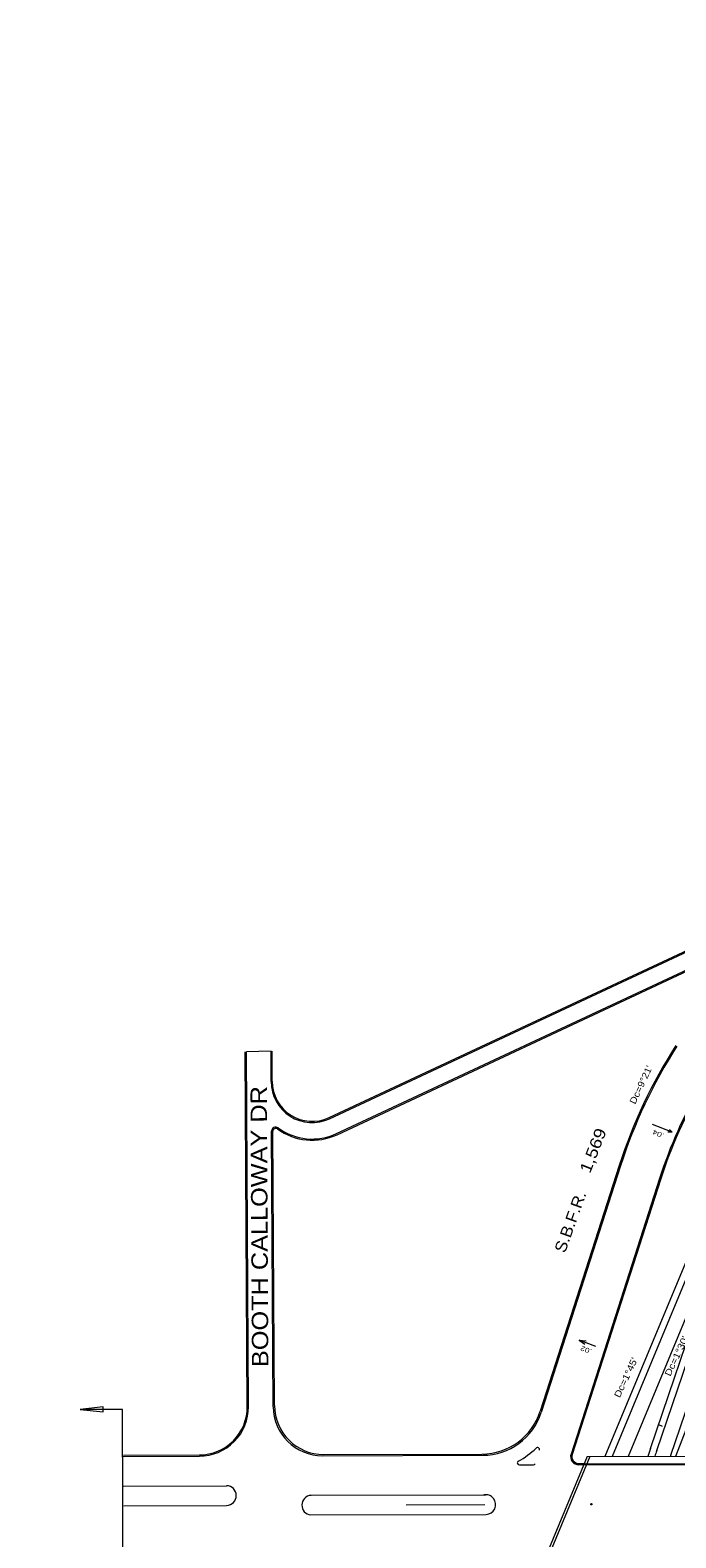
# Model space of a CAD drawing. Extents: x 2354993 to 2372084, y 6966390 to 6990057.
# Drawn here: x 2364099 to 2364884, y 6980481 to 6982315 of the extents above; entities that cross this region are included whole.
import ezdxf
from ezdxf.enums import TextEntityAlignment as Align

# ---------------------------------------------------------------- set-up
doc = ezdxf.new("R2010")
doc.units = 0
doc.header["$LTSCALE"] = 3.2
doc.header["$PDMODE"] = 32
doc.header["$PDSIZE"] = 1.6
for name, color, linetype, lineweight in [('13', 7, 'Continuous', 13), ('15', 7, 'Continuous', 13), ('17', 7, 'Continuous', 13), ('19', 7, 'Continuous', 13), ('25', 7, 'Continuous', 13), ('4', 7, 'Continuous', 13), ('5', 7, 'Continuous', 13), ('8', 7, 'Continuous', 13), ('9', 7, 'Continuous', 13)]:
    doc.layers.add(name, color=color, linetype=linetype, lineweight=lineweight)

msp = doc.modelspace()

# ---------------------------------------------------------------- linework, layer by layer
at = {"layer": '15'}
msp.add_lwpolyline([(2364212.059, 6980404.032), (2364211.303, 6980637.104), (2364159.893, 6980636.937), (2364187.903, 6980634.029), (2364187.883, 6980640.028), (2364159.893, 6980636.937)], dxfattribs=at)
at = {"layer": '19'}
for p, q in [((2364766.943, 6980721.165), (2364773.594, 6980716.189)), ((2364766.943, 6980721.165), (2364775.222, 6980720.439)), ((2364786.963, 6980713.517), (2364766.943, 6980721.165))]:
    msp.add_line(p, q, dxfattribs=at)
at = {"layer": '25'}
for p, q in [((2364391.894, 6981072.689), (2364362.145, 6981071.936)), ((2364995.931, 6981035.023), (2364806.866, 6980579.777)), ((2364861.207, 6980586.955), (2365010.841, 6981027.825)), ((2364879.743, 6980974.088), (2364856.139, 6980983.553)), ((2364879.743, 6980974.088), (2364874.732, 6980974.05)), ((2364879.743, 6980974.088), (2364876.587, 6980977.317)), ((2364815.569, 6980933.575), (2364719.53, 6980634.813)), ((2364816.997, 6980933.115), (2364720.623, 6980633.313)), ((2364864.598, 6980917.813), (2364756.875, 6980582.707)), ((2364866.026, 6980917.355), (2364757.927, 6980581.077)), ((2364868.163, 6980616.404), (2364863.537, 6980618.306)), ((2364766.423, 6980571.147), (2364773.035, 6980571.167)), ((2364766.428, 6980569.647), (2365268.294, 6980571.275))]:
    msp.add_line(p, q, dxfattribs=at)
for centre, radius, start, end in [((2365412.01, 6980741.844), 575, 137.55934, 162.17959), ((2365412.01, 6980741.844), 573.5, 137.55934, 162.17959), ((2365412.01, 6980741.844), 626.5, 147.37736, 162.17959), ((2365412.01, 6980741.844), 625, 147.37736, 162.17959), ((2364766.395, 6980579.646), 10, 162.1796, 270.18593), ((2364766.395, 6980579.646), 8.5, 162.1796, 270.18593), ((2370300.051, 6978740.971), 5743.578, 161.2524, 161.32623)]:
    msp.add_arc(centre, radius, start, end, dxfattribs=at)
at = {"layer": '4'}
for p, q in [((2364988.543, 6981038.091), (2364798.192, 6980579.749)), ((2364878.249, 6980581.158), (2365013.559, 6980979.825)), ((2364911.473, 6980784.729), (2364826.382, 6980579.841)), ((2364853.631, 6980589.527), (2364918.845, 6980781.667)), ((2364884.273, 6980580.029), (2364899.617, 6980619.817))]:
    msp.add_line(p, q, dxfattribs=at)
for centre, radius, start, end in [((2370300.051, 6978740.971), 5751.578, 161.2524, 161.35344), ((2370300.048, 6978740.957), 5725.578, 161.25239, 161.26454)]:
    msp.add_arc(centre, radius, start, end, dxfattribs=at)
at = {"layer": '5'}
for p, q in [((2364462.463, 6980991.963), (2365011.662, 6981248.793)), ((2364463.098, 6980990.605), (2365012.297, 6981247.435)), ((2364471.57, 6980972.489), (2364995.066, 6981217.297)), ((2364472.205, 6980971.129), (2364995.702, 6981215.939)), ((2364363.031, 6980640.465), (2364360.645, 6981071.95)), ((2364364.531, 6980640.473), (2364362.145, 6981071.936)), ((2364391.918, 6981035.865), (2364391.894, 6981072.689)), ((2364393.418, 6981035.867), (2364393.394, 6981072.689)), ((2364394.533, 6980640.301), (2364392.68, 6980975.305)), ((2364396.024, 6980641.812), (2364394.18, 6980975.315)), ((2364212.213, 6980579.839), (2364304.727, 6980580.141)), ((2364212.519, 6980581.341), (2364304.723, 6980581.641)), ((2364454.727, 6980580.633), (2364649.465, 6980581.266)), ((2364456.218, 6980582.144), (2364648.372, 6980582.766)), ((2364776.569, 6980579.679), (2364728.333, 6980463.531)), ((2364779.822, 6980579.689), (2364731.586, 6980463.541)), ((2364776.569, 6980579.679), (2365273.39, 6980581.292)), ((2364694.002, 6980569.411), (2364711.252, 6980569.466)), ((2364766.425, 6980570.647), (2365268.291, 6980572.275)), ((2364212.641, 6980543.847), (2364337.806, 6980544.253)), ((2364440.321, 6980532.586), (2364653.411, 6980533.278)), ((2364212.718, 6980519.849), (2364337.882, 6980520.255)), ((2364440.125, 6980508.585), (2364653.513, 6980509.278))]:
    msp.add_line(p, q, dxfattribs=at)
for centre, radius, start, end in [((2364441.918, 6981035.898), 50, 180.03669, 295.06272), ((2364441.918, 6981035.898), 48.5, 180.03669, 295.06272), ((2364397.68, 6980975.334), 5, 53.85481, 180.31682), ((2364397.68, 6980975.333), 3.5, 53.85483, 180.31682), ((2364441.918, 6981035.898), 71.5, 233.85483, 295.06321), ((2364441.918, 6981035.898), 70, 233.85481, 295.06292), ((2364304.532, 6980640.141), 58.5, 270.18698, 0.31682), ((2364304.532, 6980640.141), 60, 270.18697, 0.31682), ((2364454.532, 6980640.633), 60, 180.31685, 270.18617), ((2364456.023, 6980642.143), 60, 180.31686, 270.18557), ((2364648.129, 6980657.766), 75, 270.1855, 342.17971), ((2364649.222, 6980656.265), 75, 270.18614, 342.1796), ((2364649.222, 6980656.265), 93, 297.95774, 314.40722), ((2364716.048, 6980588.042), 2.5, 342.18249, 134.40722), ((2364693.994, 6980571.911), 2.5, 117.95774, 270.18545), ((2364711.246, 6980571.466), 2, 270.18405, 342.18207), ((2364337.694, 6980532.254), 12, 270.89854, 89.46436), ((2364441.434, 6980520.513), 12, 94.01279, 263.73872), ((2364653.272, 6980521.276), 12, 271.15204, 102.25782)]:
    msp.add_arc(centre, radius, start, end, dxfattribs=at)
at = {"layer": '8'}
msp.add_line((2364556.228, 6980520.961), (2364652.074, 6980521.273), dxfattribs=at)
at = {"layer": '9'}
msp.add_arc((2360722.521, 6984327.136), 5729.573, 359.50797, 359.50797, dxfattribs=at)
msp.add_point((2364781.691, 6980521.694), dxfattribs=at)

# ---------------------------------------------------------------- texts
at = {"layer": '13', "width": 1.15}
msp.add_text('BOOTH CALLOWAY DR', height=20, rotation=90.317, dxfattribs=at).set_placement((2364387.791, 6980859.464), align=Align.CENTER)
at = {"layer": '13'}
for s, rotation, width, p in [('1,569', 68.675, 1.2, (2364779.967, 6980923.233)), ('S.B.F.R.', 70.193, 1.1, (2364749.474, 6980826.321))]:
    msp.add_text(s, height=14, rotation=rotation, dxfattribs=dict(at, width=width)).set_placement(p)
at = {"layer": '17'}
for s, width, p in [("Dc=9°21'", 1.15, (2364834.884, 6981007.588)), ("Dc=1°30'", 1.2, (2364877.588, 6980676.573)), ("Dc=1°45'", 1.2, (2364816.082, 6980650.481))]:
    msp.add_text(s, height=8, rotation=64.778, dxfattribs=dict(at, width=width)).set_placement(p)
at = {"layer": '19'}
for s, height, rotation, width, p in [('.04', 5.999, 156.308, 1.3, (2364871.003, 6980971.987)), ('.02', 6, 159.133, 1.25, (2364782.821, 6980709.764))]:
    msp.add_text(s, height=height, rotation=rotation, dxfattribs=dict(at, width=width)).set_placement(p)

doc.saveas('drawing.dxf')
